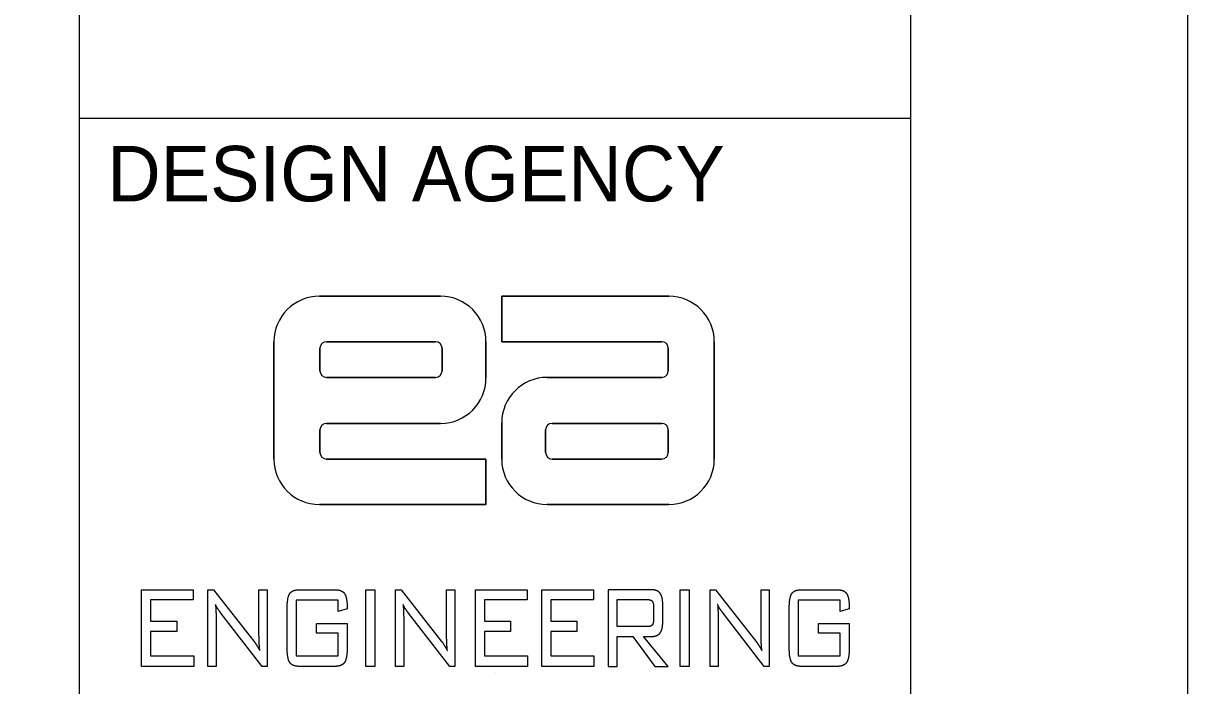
# Model space of a CAD drawing. Extents: x -4.5 to 38.8, y 0 to 22.
# Drawn here: x 31.899 to 34, y 3.476 to 4.671 of the extents above; entities that cross this region are included whole.
import ezdxf

# ---------------------------------------------------------------- set-up
doc = ezdxf.new("R2010")
doc.units = 0
for name, color, linetype in [('SH_Border', 7, 'Continuous'), ('SH_Cut_Line', 7, 'Continuous'), ('SH_Data', 7, 'Continuous'), ('TX_X_20', 7, 'Continuous')]:
    doc.layers.add(name, color=color, linetype=linetype)

msp = doc.modelspace()

# ---------------------------------------------------------------- linework, layer by layer
at = {"layer": 'SH_Border'}
for p, q in [((32, 0.5), (32, 21.5)), ((32, 4.5), (33.5, 4.5))]:
    msp.add_line(p, q, dxfattribs=at)
msp.add_lwpolyline([(1.5, 21.5), (33.5, 21.5), (33.5, 0.5), (1.5, 0.5)], close=True, dxfattribs=at)
at = {"layer": 'SH_Cut_Line'}
msp.add_lwpolyline([(0, 0), (34, 0), (34, 22), (0, 22)], close=True, dxfattribs=at)
at = {"layer": 'SH_Data'}
msp.add_line((32.75, 3.5), (32.75, 3.5), dxfattribs=at)
at = {"layer": 'TX_X_20'}
for p, q in [((32.6515, 4.1788), (32.433, 4.1788)), ((32.433, 4.1788), (32.6515, 4.1788)), ((32.762, 4.1788), (33.0635, 4.1788)), ((32.762, 4.0967), (32.762, 4.1788)), ((32.351, 4.0967), (32.351, 3.8852)), ((32.351, 3.8852), (32.351, 4.0967)), ((32.434, 4.0444), (32.434, 4.0849)), ((32.434, 4.0849), (32.434, 4.0444)), ((32.4459, 4.0967), (32.6426, 4.0967)), ((32.6426, 4.0967), (32.4459, 4.0967)), ((32.6545, 4.0849), (32.6545, 4.0444)), ((32.6545, 4.0444), (32.6545, 4.0849)), ((32.7336, 4.0315), (32.7336, 4.0967)), ((32.7336, 4.0967), (32.7336, 4.0315)), ((33.0507, 4.0967), (32.762, 4.0967)), ((33.0626, 4.0849), (33.0626, 4.0444)), ((33.0626, 4.0444), (33.0626, 4.0849)), ((33.1456, 3.8852), (33.1456, 4.0967)), ((33.1456, 4.0967), (33.1456, 3.8852)), ((32.6426, 4.0325), (32.4459, 4.0325)), ((32.4459, 4.0325), (32.6426, 4.0325)), ((33.0507, 4.0325), (32.8441, 4.0325)), ((32.8441, 4.0325), (33.0507, 4.0325)), ((32.434, 3.8971), (32.434, 3.9376)), ((32.434, 3.9376), (32.434, 3.8971)), ((32.4459, 3.9494), (32.6515, 3.9494)), ((32.6515, 3.9494), (32.4459, 3.9494)), ((32.762, 3.9504), (32.762, 3.8852)), ((32.762, 3.8852), (32.762, 3.9504)), ((32.8411, 3.8971), (32.8411, 3.9376)), ((32.8411, 3.9376), (32.8411, 3.8971)), ((32.853, 3.9494), (33.0507, 3.9494)), ((33.0507, 3.9494), (32.853, 3.9494)), ((33.0626, 3.9376), (33.0626, 3.8971)), ((33.0626, 3.8971), (33.0626, 3.9376)), ((32.4459, 3.8852), (32.7336, 3.8852)), ((32.7336, 3.8852), (32.7336, 3.8031)), ((33.0507, 3.8852), (32.853, 3.8852)), ((32.853, 3.8852), (33.0507, 3.8852)), ((32.7336, 3.8031), (32.433, 3.8031)), ((32.8441, 3.8031), (33.0635, 3.8031)), ((33.0635, 3.8031), (32.8441, 3.8031)), ((32.3975, 3.6495), (32.4602, 3.6495)), ((33.3037, 3.6495), (33.3663, 3.6495)), ((32.3748, 3.5439), (32.3748, 3.6168)), ((33.0361, 3.6173), (33.0361, 3.5971)), ((33.0526, 3.5917), (33.0526, 3.6227)), ((33.2809, 3.5439), (33.2809, 3.6168)), ((32.4602, 3.5111), (32.3975, 3.5111)), ((33.3663, 3.5111), (33.3037, 3.5111))]:
    msp.add_line(p, q, dxfattribs=at)
for points in [[(33.0635, 4.1788), (32.762, 4.1788), (32.762, 4.0967), (33.0507, 4.0967)], [(32.433, 3.8031), (32.7336, 3.8031), (32.7336, 3.8852), (32.4459, 3.8852)], [(32.2465, 3.5927), (32.2465, 3.5111), (32.2317, 3.5111), (32.2317, 3.6495), (32.2419, 3.6495), (32.3144, 3.5569)], [(32.3239, 3.5736), (32.3239, 3.6495), (32.3387, 3.6495), (32.3387, 3.5111), (32.3297, 3.5111), (32.2553, 3.6074)], [(32.5851, 3.5927), (32.5851, 3.5111), (32.5703, 3.5111), (32.5703, 3.6495), (32.5804, 3.6495), (32.6529, 3.5569)], [(32.6625, 3.5736), (32.6625, 3.6495), (32.6773, 3.6495), (32.6773, 3.5111), (32.6682, 3.5111), (32.5938, 3.6074)], [(33.032, 3.6495), (32.954, 3.6495), (32.954, 3.5111), (32.9702, 3.5111), (32.9702, 3.565), (32.9987, 3.565), (33.0381, 3.5111), (33.0621, 3.5111), (33.0178, 3.565), (33.032, 3.565)], [(33.1527, 3.5927), (33.1527, 3.5111), (33.1379, 3.5111), (33.1379, 3.6495), (33.148, 3.6495), (33.2205, 3.5569)], [(33.2301, 3.5736), (33.2301, 3.6495), (33.2449, 3.6495), (33.2449, 3.5111), (33.2358, 3.5111), (33.1614, 3.6074)], [(32.483, 3.6183), (32.483, 3.6149), (32.4668, 3.6103), (32.4668, 3.6307), (32.3909, 3.6307), (32.3909, 3.5304), (32.4668, 3.5304), (32.4668, 3.571), (32.4276, 3.571), (32.4276, 3.5886), (32.483, 3.5886), (32.483, 3.5439)], [(33.0257, 3.5829), (32.9702, 3.5829), (32.9702, 3.6316), (33.0257, 3.6316)], [(33.3891, 3.6183), (33.3891, 3.6149), (33.3729, 3.6103), (33.3729, 3.6307), (33.2971, 3.6307), (33.2971, 3.5304), (33.3729, 3.5304), (33.3729, 3.571), (33.3338, 3.571), (33.3338, 3.5886), (33.3891, 3.5886), (33.3891, 3.5439)]]:
    msp.add_lwpolyline(points, dxfattribs=at)
for points in [[(32.1121, 3.5111), (32.1121, 3.6495), (32.2053, 3.6495), (32.2053, 3.631), (32.1283, 3.631), (32.1283, 3.5925), (32.1754, 3.5925), (32.1754, 3.5742), (32.1283, 3.5742), (32.1283, 3.5301), (32.2061, 3.5301), (32.2061, 3.5111)], [(32.5166, 3.5111), (32.5166, 3.6495), (32.5329, 3.6495), (32.5329, 3.5111)], [(32.7147, 3.5111), (32.7147, 3.6495), (32.8079, 3.6495), (32.8079, 3.631), (32.7309, 3.631), (32.7309, 3.5925), (32.778, 3.5925), (32.778, 3.5742), (32.7309, 3.5742), (32.7309, 3.5301), (32.8087, 3.5301), (32.8087, 3.5111)], [(32.8343, 3.5111), (32.8343, 3.6495), (32.9276, 3.6495), (32.9276, 3.631), (32.8506, 3.631), (32.8506, 3.5925), (32.8977, 3.5925), (32.8977, 3.5742), (32.8506, 3.5742), (32.8506, 3.5301), (32.9283, 3.5301), (32.9283, 3.5111)], [(33.0842, 3.5111), (33.0842, 3.6495), (33.1005, 3.6495), (33.1005, 3.5111)]]:
    msp.add_lwpolyline(points, close=True, dxfattribs=at)
for centre, radius, start, end in [((32.433, 4.0967), 0.0821, 90, 180), ((32.433, 4.0967), 0.0821, 90, 180), ((32.6515, 4.0967), 0.0821, 0, 90), ((32.6515, 4.0967), 0.0821, 0, 90), ((33.0635, 4.0967), 0.0821, 0, 90), ((33.0635, 4.0967), 0.0821, 0, 90), ((32.4459, 4.0849), 0.0119, 90, 180), ((32.4459, 4.0849), 0.0119, 90, 180), ((32.6426, 4.0849), 0.0119, 0, 90), ((32.6426, 4.0849), 0.0119, 0, 90), ((33.0507, 4.0849), 0.0119, 0, 90), ((33.0507, 4.0849), 0.0119, 0, 90), ((32.4459, 4.0444), 0.0119, 180, 270), ((32.4459, 4.0444), 0.0119, 180, 270), ((32.6426, 4.0444), 0.0119, 270, 0), ((32.6426, 4.0444), 0.0119, 270, 0), ((33.0507, 4.0444), 0.0119, 270, 0), ((33.0507, 4.0444), 0.0119, 270, 0), ((32.6515, 4.0315), 0.0821, 270, 360), ((32.6515, 4.0315), 0.0821, 270, 360), ((32.8441, 3.9504), 0.0821, 90, 180), ((32.8441, 3.9504), 0.0821, 90, 180), ((32.4459, 3.9376), 0.0119, 90, 180), ((32.4459, 3.9376), 0.0119, 90, 180), ((32.853, 3.9376), 0.0119, 90, 180), ((32.853, 3.9376), 0.0119, 90, 180), ((33.0507, 3.9376), 0.0119, 0, 90), ((33.0507, 3.9376), 0.0119, 0, 90), ((32.4459, 3.8971), 0.0119, 180, 270), ((32.4459, 3.8971), 0.0119, 180, 270), ((32.853, 3.8971), 0.0119, 180, 270), ((32.853, 3.8971), 0.0119, 180, 270), ((33.0507, 3.8971), 0.0119, 270, 0), ((33.0507, 3.8971), 0.0119, 270, 0), ((32.433, 3.8852), 0.0821, 180, 270), ((32.433, 3.8852), 0.0821, 180, 270), ((32.8441, 3.8852), 0.0821, 180, 270), ((32.8441, 3.8852), 0.0821, 180, 270), ((33.0635, 3.8852), 0.0821, 270, 360), ((33.0635, 3.8852), 0.0821, 270, 360)]:
    msp.add_arc(centre, radius, start, end, dxfattribs=at)
for points in [[(32.3748, 3.6168), (32.3748, 3.6356), (32.3795, 3.6426)], [(32.3795, 3.6426), (32.3842, 3.6495), (32.3975, 3.6495)], [(32.4602, 3.6495), (32.4732, 3.6495), (32.4781, 3.6428)], [(32.4781, 3.6428), (32.483, 3.636), (32.483, 3.6183)], [(33.0477, 3.6432), (33.0429, 3.6495), (33.032, 3.6495)], [(33.0526, 3.6227), (33.0526, 3.6368), (33.0477, 3.6432)], [(33.2809, 3.6168), (33.2809, 3.6356), (33.2857, 3.6426)], [(33.2857, 3.6426), (33.2904, 3.6495), (33.3037, 3.6495)], [(33.3663, 3.6495), (33.3794, 3.6495), (33.3842, 3.6428)], [(33.3842, 3.6428), (33.3891, 3.636), (33.3891, 3.6183)], [(32.2536, 3.6094), (32.2481, 3.6165), (32.2454, 3.6229)], [(32.2454, 3.6229), (32.246, 3.6166), (32.2463, 3.6095)], [(32.5921, 3.6094), (32.5866, 3.6165), (32.584, 3.6229)], [(32.584, 3.6229), (32.5845, 3.6166), (32.5848, 3.6095)], [(33.0257, 3.6316), (33.0316, 3.6316), (33.0339, 3.6284)], [(33.0339, 3.6284), (33.0361, 3.6252), (33.0361, 3.6173)], [(33.1597, 3.6094), (33.1542, 3.6165), (33.1516, 3.6229)], [(33.1516, 3.6229), (33.1521, 3.6166), (33.1524, 3.6095)], [(32.2463, 3.6095), (32.2465, 3.6024), (32.2465, 3.5927)], [(32.2553, 3.6074), (32.2547, 3.608), (32.2536, 3.6094)], [(32.5848, 3.6095), (32.5851, 3.6024), (32.5851, 3.5927)], [(32.5938, 3.6074), (32.5932, 3.608), (32.5921, 3.6094)], [(33.0361, 3.5971), (33.0361, 3.5892), (33.0339, 3.5861)], [(33.1524, 3.6095), (33.1527, 3.6024), (33.1527, 3.5927)], [(33.1614, 3.6074), (33.1608, 3.608), (33.1597, 3.6094)], [(32.3243, 3.5535), (32.3239, 3.5607), (32.3239, 3.5736)], [(32.6628, 3.5535), (32.6625, 3.5607), (32.6625, 3.5736)], [(33.0339, 3.5861), (33.0317, 3.5829), (33.0257, 3.5829)], [(33.0477, 3.5714), (33.0526, 3.5777), (33.0526, 3.5917)], [(33.2304, 3.5535), (33.2301, 3.5607), (33.2301, 3.5736)], [(32.3144, 3.5569), (32.3169, 3.5538), (32.3197, 3.5493)], [(32.3254, 3.5395), (32.3247, 3.5462), (32.3243, 3.5535)], [(32.6529, 3.5569), (32.6554, 3.5538), (32.6582, 3.5493)], [(32.6639, 3.5395), (32.6632, 3.5462), (32.6628, 3.5535)], [(33.032, 3.565), (33.0429, 3.565), (33.0477, 3.5714)], [(33.2205, 3.5569), (33.223, 3.5538), (33.2258, 3.5493)], [(33.2315, 3.5395), (33.2308, 3.5462), (33.2304, 3.5535)], [(32.3197, 3.5493), (32.3225, 3.5449), (32.3254, 3.5395)], [(32.3795, 3.5181), (32.3748, 3.525), (32.3748, 3.5439)], [(32.483, 3.5439), (32.483, 3.5249), (32.4782, 3.518)], [(32.6582, 3.5493), (32.661, 3.5449), (32.6639, 3.5395)], [(33.2258, 3.5493), (33.2286, 3.5449), (33.2315, 3.5395)], [(33.2857, 3.5181), (33.2809, 3.525), (33.2809, 3.5439)], [(33.3891, 3.5439), (33.3891, 3.5249), (33.3843, 3.518)], [(32.3975, 3.5111), (32.3842, 3.5111), (32.3795, 3.5181)], [(32.4782, 3.518), (32.4734, 3.5111), (32.4602, 3.5111)], [(33.3037, 3.5111), (33.2904, 3.5111), (33.2857, 3.5181)], [(33.3843, 3.518), (33.3795, 3.5111), (33.3663, 3.5111)]]:
    msp.add_open_spline(points, degree=2, dxfattribs=at)

# ---------------------------------------------------------------- texts
at = {"layer": 'SH_Data'}
msp.add_text('DESIGN AGENCY', height=0.1, dxfattribs=at).set_placement((32.05, 4.35))

doc.saveas('drawing.dxf')
